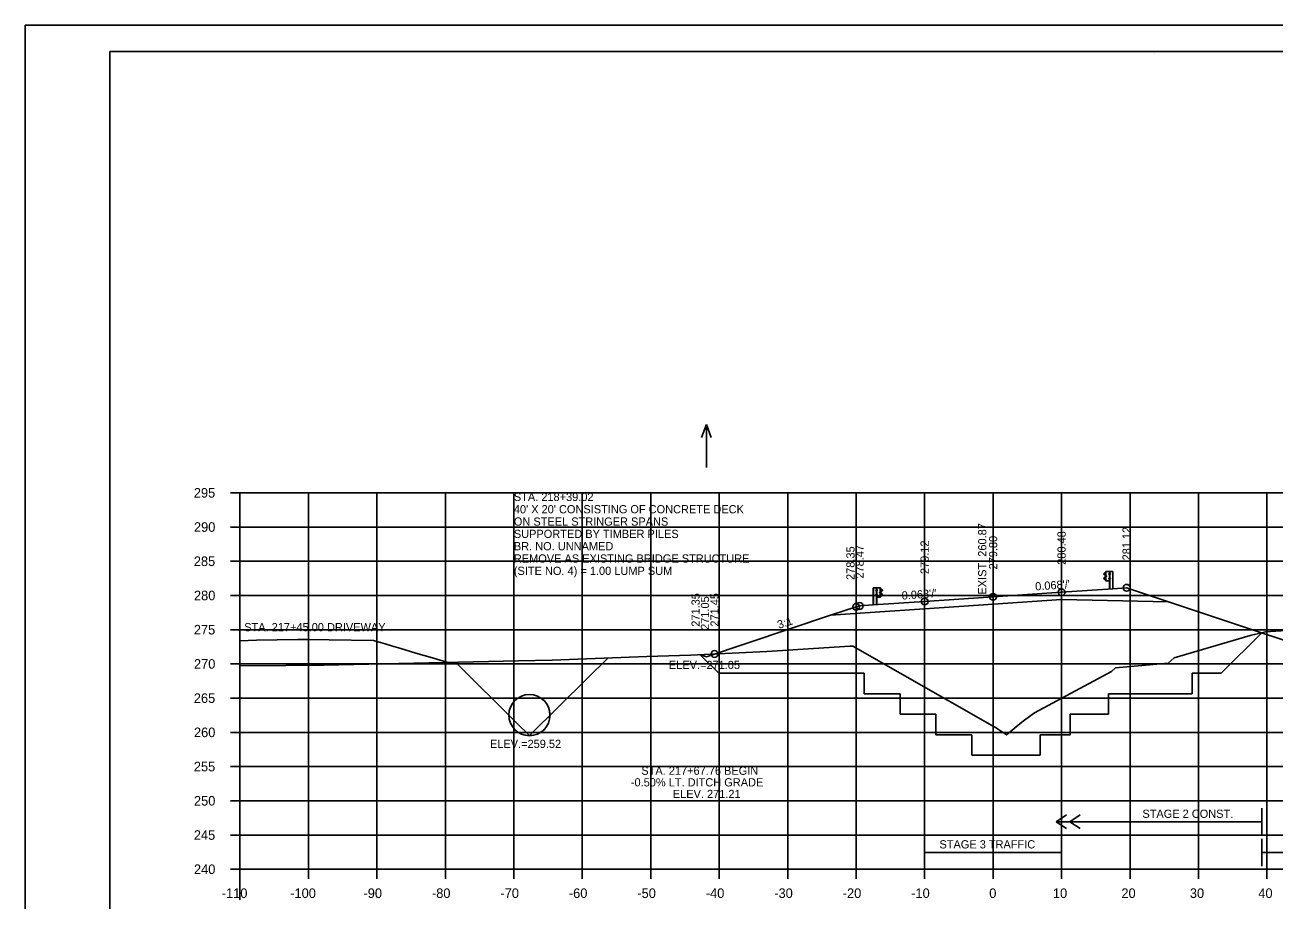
# Model space of a CAD drawing. Extents: x 4667 to 1632277, y -2100 to 724501.
# Drawn here: x 5635.8 to 5818.2, y -1024.9 to -897.1 of the extents above; entities that cross this region are included whole.
import ezdxf

# ---------------------------------------------------------------- set-up
doc = ezdxf.new("R2010")
doc.units = 0
for name, color, linetype in [('R_Alt Surface', 7, 'Continuous'), ('R_Axis', 7, 'Continuous'), ('R_Axis Annot', 7, 'Continuous'), ('R_Border', 7, 'Continuous'), ('R_Draft', 7, 'Continuous'), ('R_Drive', 7, 'Continuous'), ('R_Exist Surface', 7, 'Continuous'), ('R_Fin Surface', 7, 'Continuous'), ('R_Fin Surface Annot', 7, 'Continuous'), ('R_Grid', 7, 'Continuous'), ('R_No Plot', 7, 'Continuous'), ('R_Proposed CofA', 7, 'Continuous'), ('R_ROW', 7, 'Continuous'), ('R_Temp Easement', 7, 'Continuous'), ('R_Water', 7, 'Continuous'), ('R_Water Annot', 7, 'Continuous'), ('R_Xsect Elev', 7, 'Continuous')]:
    doc.layers.add(name, color=color, linetype=linetype)

msp = doc.modelspace()

# ---------------------------------------------------------------- linework, layer by layer
at = {"layer": 'R_Alt Surface'}
msp.add_lwpolyline([(5753.44, -983.33), (5767.18, -982.4), (5777.18, -981.72), (5787.18, -981.04), (5802.81, -981.35)], dxfattribs=at)
at = {"layer": 'R_Axis'}
for p, q in [((5665.78, -965.43), (5667.18, -965.43)), ((5667.18, -1020.43), (5667.18, -965.43)), ((5665.78, -970.43), (5667.18, -970.43)), ((5665.78, -975.43), (5667.18, -975.43)), ((5665.78, -980.43), (5667.18, -980.43)), ((5665.78, -985.43), (5667.18, -985.43)), ((5665.78, -990.43), (5667.18, -990.43)), ((5665.78, -995.43), (5667.18, -995.43)), ((5665.78, -1000.43), (5667.18, -1000.43)), ((5665.78, -1005.43), (5667.18, -1005.43)), ((5665.78, -1010.43), (5667.18, -1010.43)), ((5665.78, -1015.43), (5667.18, -1015.43)), ((5665.78, -1020.43), (5667.18, -1020.43)), ((5667.18, -1020.43), (5947.18, -1020.43)), ((5667.18, -1021.83), (5667.18, -1020.43)), ((5677.18, -1021.83), (5677.18, -1020.43)), ((5687.18, -1021.83), (5687.18, -1020.43)), ((5697.18, -1021.83), (5697.18, -1020.43)), ((5707.18, -1021.83), (5707.18, -1020.43)), ((5717.18, -1021.83), (5717.18, -1020.43)), ((5727.18, -1021.83), (5727.18, -1020.43)), ((5737.18, -1021.83), (5737.18, -1020.43)), ((5747.18, -1021.83), (5747.18, -1020.43)), ((5757.18, -1021.83), (5757.18, -1020.43)), ((5767.18, -1021.83), (5767.18, -1020.43)), ((5777.18, -1021.83), (5777.18, -1020.43)), ((5787.18, -1021.83), (5787.18, -1020.43)), ((5797.18, -1021.83), (5797.18, -1020.43)), ((5807.18, -1021.83), (5807.18, -1020.43)), ((5817.18, -1021.83), (5817.18, -1020.43))]:
    msp.add_line(p, q, dxfattribs=at)
at = {"layer": 'R_Border'}
for p, q in [((5648.18, -900.97), (5964.36, -900.97)), ((5648.18, -1106.43), (5648.18, -900.97)), ((5800.7, -901.23), (5800.7, -901.23)), ((5800.7, -901.23), (5800.7, -901.23))]:
    msp.add_line(p, q, dxfattribs=at)
at = {"layer": 'R_Draft'}
for p, q in [((5793.39, -977.25), (5793.52, -977.14)), ((5793.56, -977.49), (5793.39, -977.39)), ((5793.4, -977.26), (5793.53, -977.16)), ((5793.57, -977.47), (5793.4, -977.37)), ((5793.41, -977.83), (5793.57, -977.73)), ((5793.42, -977.85), (5793.58, -977.75)), ((5793.52, -977.14), (5793.63, -977.08)), ((5793.53, -977.16), (5793.62, -977.11)), ((5793.6, -977.67), (5793.6, -977.54)), ((5793.62, -977.67), (5793.62, -977.54)), ((5793.66, -978.29), (5793.66, -976.93)), ((5793.67, -977.67), (5793.67, -977.55)), ((5793.67, -977.55), (5793.72, -977.55)), ((5793.67, -977.58), (5793.72, -977.58)), ((5793.67, -977.64), (5793.72, -977.64)), ((5793.67, -977.64), (5793.72, -977.64)), ((5793.67, -977.67), (5793.72, -977.67)), ((5793.73, -977.66), (5793.73, -977.56)), ((5794.15, -977.23), (5794.1, -977.23)), ((5794.1, -977.23), (5794.1, -977.36)), ((5794.1, -977.3), (5794.16, -977.3)), ((5794.15, -977.36), (5794.1, -977.36)), ((5794.16, -976.93), (5794.17, -976.93)), ((5794.16, -976.93), (5794.23, -976.93)), ((5794.19, -979.44), (5794.19, -976.93)), ((5794.23, -977.35), (5794.23, -977.23)), ((5794.23, -977.23), (5794.28, -977.23)), ((5794.23, -977.26), (5794.28, -977.26)), ((5794.23, -977.32), (5794.27, -977.32)), ((5794.23, -977.32), (5794.28, -977.32)), ((5794.23, -977.35), (5794.28, -977.35)), ((5794.28, -977.34), (5794.28, -977.24)), ((5794.65, -976.93), (5794.65, -979.44)), ((5794.68, -976.93), (5794.68, -979.44)), ((5759.68, -979.31), (5759.68, -981.82)), ((5759.71, -979.31), (5759.71, -981.82)), ((5760.08, -979.72), (5760.08, -979.62)), ((5760.14, -979.61), (5760.09, -979.61)), ((5760.14, -979.64), (5760.09, -979.64)), ((5760.21, -979.31), (5760.14, -979.31)), ((5760.14, -979.73), (5760.14, -979.61)), ((5760.18, -981.82), (5760.18, -979.31)), ((5760.21, -979.31), (5760.2, -979.31)), ((5760.26, -979.68), (5760.21, -979.68)), ((5760.22, -979.61), (5760.27, -979.61)), ((5760.27, -979.61), (5760.27, -979.74)), ((5760.71, -980.67), (5760.71, -979.31)), ((5760.85, -979.52), (5760.74, -979.46)), ((5760.84, -979.54), (5760.75, -979.49)), ((5760.97, -979.64), (5760.84, -979.54)), ((5760.98, -979.63), (5760.85, -979.52)), ((5793.51, -978.09), (5793.38, -977.98)), ((5793.52, -978.08), (5793.4, -977.97)), ((5793.62, -978.15), (5793.51, -978.09)), ((5793.63, -978.13), (5793.52, -978.08)), ((5794.1, -978.04), (5794.1, -977.92)), ((5794.1, -977.92), (5794.15, -977.92)), ((5794.1, -977.98), (5794.16, -977.98)), ((5794.1, -978.04), (5794.15, -978.04)), ((5794.16, -978.29), (5794.19, -978.29)), ((5794.24, -978.04), (5794.24, -977.92)), ((5794.24, -977.92), (5794.29, -977.92)), ((5794.24, -977.95), (5794.29, -977.95)), ((5794.24, -978.01), (5794.28, -978.01)), ((5794.24, -978.01), (5794.29, -978.01)), ((5794.24, -978.04), (5794.29, -978.04)), ((5794.29, -978.03), (5794.29, -977.93)), ((5760.07, -980.41), (5760.07, -980.31)), ((5760.13, -980.3), (5760.08, -980.3)), ((5760.13, -980.33), (5760.08, -980.33)), ((5760.13, -980.39), (5760.08, -980.39)), ((5760.13, -980.42), (5760.08, -980.42)), ((5760.14, -979.7), (5760.09, -979.7)), ((5760.14, -979.73), (5760.09, -979.73)), ((5760.13, -980.39), (5760.09, -980.39)), ((5760.14, -979.7), (5760.1, -979.7)), ((5760.13, -980.42), (5760.13, -980.3)), ((5760.21, -980.67), (5760.17, -980.67)), ((5760.26, -980.36), (5760.21, -980.36)), ((5760.22, -979.74), (5760.27, -979.74)), ((5760.27, -980.3), (5760.22, -980.3)), ((5760.27, -980.42), (5760.22, -980.42)), ((5760.27, -980.42), (5760.27, -980.3)), ((5760.64, -980.04), (5760.64, -979.95)), ((5760.7, -979.93), (5760.65, -979.93)), ((5760.7, -979.96), (5760.65, -979.96)), ((5760.7, -980.03), (5760.65, -980.03)), ((5760.7, -980.03), (5760.65, -980.03)), ((5760.7, -980.06), (5760.65, -980.06)), ((5760.7, -980.06), (5760.7, -979.93)), ((5760.74, -980.51), (5760.84, -980.46)), ((5760.74, -980.53), (5760.86, -980.47)), ((5760.75, -980.05), (5760.75, -979.92)), ((5760.77, -980.06), (5760.77, -979.92)), ((5760.79, -979.85), (5760.97, -979.75)), ((5760.94, -980.23), (5760.79, -980.13)), ((5760.96, -980.21), (5760.8, -980.11)), ((5760.81, -979.88), (5760.98, -979.77)), ((5760.84, -980.46), (5760.97, -980.35)), ((5760.86, -980.47), (5760.98, -980.36))]:
    msp.add_line(p, q, dxfattribs=at)
for points in [[(5793.63, -976.93), (5793.64, -978.29), (5794.16, -978.29), (5794.16, -976.93)], [(5793.67, -977.53), (5793.67, -977.7), (5793.66, -977.7), (5793.66, -977.53)], [(5793.73, -977.58), (5793.73, -977.64), (5793.76, -977.64), (5793.76, -977.58)], [(5794.1, -977.23), (5794.1, -977.36), (5794.16, -977.36), (5794.16, -977.23)], [(5794.23, -977.21), (5794.23, -977.38), (5794.22, -977.38), (5794.22, -977.21)], [(5794.29, -977.26), (5794.29, -977.32), (5794.31, -977.32), (5794.31, -977.26)], [(5760.08, -979.64), (5760.08, -979.7), (5760.06, -979.7), (5760.06, -979.64)], [(5760.14, -979.59), (5760.14, -979.76), (5760.15, -979.76), (5760.15, -979.59)], [(5760.73, -979.31), (5760.73, -980.67), (5760.21, -980.67), (5760.21, -979.31)], [(5760.26, -979.61), (5760.26, -979.74), (5760.21, -979.74), (5760.21, -979.61)], [(5794.1, -977.92), (5794.1, -978.04), (5794.16, -978.04), (5794.16, -977.92)], [(5794.24, -977.9), (5794.24, -978.07), (5794.23, -978.07), (5794.23, -977.9)], [(5794.3, -977.95), (5794.3, -978.01), (5794.32, -978.01), (5794.32, -977.95)], [(5760.07, -980.33), (5760.07, -980.39), (5760.05, -980.39), (5760.05, -980.33)], [(5760.13, -980.28), (5760.13, -980.45), (5760.14, -980.45), (5760.14, -980.28)], [(5760.26, -980.3), (5760.26, -980.42), (5760.21, -980.42), (5760.21, -980.3)], [(5760.64, -979.96), (5760.64, -980.02), (5760.61, -980.02), (5760.61, -979.96)], [(5760.69, -979.91), (5760.69, -980.08), (5760.7, -980.08), (5760.7, -979.91)]]:
    msp.add_lwpolyline(points, close=True, dxfattribs=at)
for points in [[(5794.68, -976.93), (5794.23, -976.93), (5794.23, -979.44)], [(5759.68, -979.31), (5760.14, -979.31), (5760.14, -981.82)]]:
    msp.add_lwpolyline(points, dxfattribs=at)
for centre, radius, start, end in [((5793.43, -977.31), 0.0856, 122.0217, 240.7501), ((5793.47, -977.92), 0.109, 120.88, 214.7816), ((5793.43, -977.31), 0.062, 122.0217, 240.7501), ((5793.47, -977.92), 0.0854, 120.88, 214.7816), ((5793.53, -977.55), 0.0622, 4.9556, 61.894), ((5793.6, -977.62), 0.0453, 93.9303, 257.0446), ((5793.53, -977.55), 0.0865, 4.9556, 61.894), ((5793.55, -977.68), 0.0462, 293.1464, 8.2196), ((5793.55, -977.68), 0.0703, 293.1464, 8.2196), ((5793.71, -977.57), 0.022, 317.7756, 45.4255), ((5793.64, -977.61), 0.0922, 339.7423, 20.2577), ((5793.7, -977.66), 0.025, 323.3766, 39.0666), ((5794.26, -977.24), 0.022, 317.7756, 45.4255), ((5794.19, -977.29), 0.0922, 339.7423, 20.2577), ((5794.26, -977.34), 0.025, 323.3766, 39.0666), ((5760.11, -979.62), 0.022, 134.5745, 222.2244), ((5760.18, -979.67), 0.0922, 159.7423, 200.2577), ((5760.94, -979.7), 0.062, 299.2499, 57.9783), ((5760.94, -979.7), 0.0856, 299.2499, 57.9783), ((5794.27, -977.93), 0.022, 317.7756, 45.4255), ((5794.2, -977.98), 0.0922, 339.7423, 20.2577), ((5794.27, -978.03), 0.025, 323.3766, 39.0666), ((5760.1, -980.31), 0.022, 134.5745, 222.2244), ((5760.17, -980.36), 0.0922, 159.7423, 200.2577), ((5760.1, -980.41), 0.025, 140.9334, 216.6234), ((5760.11, -979.72), 0.025, 140.9334, 216.6234), ((5760.66, -979.95), 0.022, 134.5745, 222.2244), ((5760.73, -979.99), 0.0922, 159.7423, 200.2577), ((5760.67, -980.04), 0.025, 140.9334, 216.6234), ((5760.84, -979.93), 0.0865, 118.106, 175.0444), ((5760.82, -980.06), 0.0703, 171.7804, 246.8536), ((5760.84, -979.93), 0.0622, 118.106, 175.0444), ((5760.77, -980), 0.0453, 282.9554, 86.0697), ((5760.82, -980.06), 0.0462, 171.7804, 246.8536), ((5760.9, -980.3), 0.0854, 325.2184, 59.12), ((5760.9, -980.3), 0.109, 325.2184, 59.12)]:
    msp.add_arc(centre, radius, start, end, dxfattribs=at)
at = {"layer": 'R_Drive'}
msp.add_lwpolyline([(5667.18, -987.04), (5669.58, -986.98), (5675.63, -986.85), (5677.1, -986.87), (5680.22, -986.91), (5686.68, -987), (5688.39, -987.51), (5689.32, -987.79), (5690.68, -988.19), (5692.88, -988.85), (5695.3, -989.55), (5697.56, -990.21)], dxfattribs=at)
at = {"layer": 'R_Exist Surface'}
msp.add_lwpolyline([(5667.18, -990.7), (5673.88, -990.67), (5679.47, -990.62), (5683.82, -990.53), (5707.87, -989.97), (5712.76, -989.86), (5726.62, -989.37), (5732.99, -989.15), (5744.12, -988.61), (5756.26, -987.86), (5756.71, -987.83), (5777.42, -999.69), (5777.79, -999.89), (5777.84, -999.9), (5779.15, -1000.78), (5781.39, -998.92), (5782.88, -997.83), (5783.22, -997.6), (5794.48, -991.54), (5795.07, -990.99), (5802.75, -990.33), (5803.65, -989.56), (5814.73, -986.26), (5816.96, -985.76), (5822.23, -985.39)], dxfattribs=at)
at = {"layer": 'R_Fin Surface'}
msp.add_lwpolyline([(5734.4, -989.08), (5735.3, -989.38), (5753.44, -983.33), (5757.18, -982.08), (5757.68, -981.96), (5759.68, -981.82), (5767.18, -981.31), (5777.18, -980.63), (5787.18, -979.95), (5794.68, -979.44), (5796.68, -979.31), (5802.81, -981.35), (5862.19, -1001.14), (5897.19, -1001.14), (5918.54, -994.02)], dxfattribs=at)
at = {"layer": 'R_Grid'}
for p, q in [((5667.18, -965.43), (5947.18, -965.43)), ((5667.18, -1020.43), (5667.18, -965.43)), ((5677.18, -1020.43), (5677.18, -965.43)), ((5687.18, -1020.43), (5687.18, -965.43)), ((5697.18, -1020.43), (5697.18, -965.43)), ((5707.18, -1020.43), (5707.18, -965.43)), ((5717.18, -1020.43), (5717.18, -965.43)), ((5727.18, -1020.43), (5727.18, -965.43)), ((5737.18, -1020.43), (5737.18, -965.43)), ((5747.18, -1020.43), (5747.18, -965.43)), ((5757.18, -1020.43), (5757.18, -965.43)), ((5767.18, -1020.43), (5767.18, -965.43)), ((5777.18, -1020.43), (5777.18, -965.43)), ((5787.18, -1020.43), (5787.18, -965.43)), ((5797.18, -1020.43), (5797.18, -965.43)), ((5807.18, -1020.43), (5807.18, -965.43)), ((5817.18, -1020.43), (5817.18, -965.43)), ((5667.18, -970.43), (5947.18, -970.43)), ((5667.18, -975.43), (5947.18, -975.43)), ((5667.18, -980.43), (5947.18, -980.43)), ((5667.18, -985.43), (5947.18, -985.43)), ((5667.18, -990.43), (5947.18, -990.43)), ((5667.18, -995.43), (5947.18, -995.43)), ((5667.18, -1000.43), (5947.18, -1000.43)), ((5667.18, -1005.43), (5947.18, -1005.43)), ((5667.18, -1010.43), (5947.18, -1010.43)), ((5667.18, -1015.43), (5947.18, -1015.43)), ((5667.18, -1020.43), (5947.18, -1020.43))]:
    msp.add_line(p, q, dxfattribs=at)
at = {"layer": 'R_No Plot'}
for p, q in [((5635.78, -897.08), (5969.12, -897.08)), ((5667.18, -1021.83), (5667.18, -1024.9))]:
    msp.add_line(p, q, dxfattribs=at)
for points in [[(5635.78, -897.08), (5969.12, -897.08), (5969.12, -1110.41), (5635.78, -1110.41)], [(5882.1, -900.97), (5901.72, -900.97), (5901.72, -910.85), (5917.84, -910.85), (5941.04, -910.85), (5941.04, -935.18), (5964.36, -935.18), (5964.36, -1106.43), (5648.18, -1106.43), (5648.18, -900.97)]]:
    msp.add_lwpolyline(points, close=True, dxfattribs=at)
msp.add_lwpolyline([(5698.67, -990.19), (5707.62, -999.08), (5709.46, -1000.91), (5717.99, -992.44), (5720.89, -989.57)], dxfattribs=at)
for centre, radius in [((5787.18, -979.95), 0.5), ((5796.68, -979.31), 0.5), ((5796.68, -979.31), 0.5), ((5757.68, -981.96), 0.5), ((5767.18, -981.31), 0.5), ((5777.18, -980.63), 0.5), ((5757.18, -982.08), 0.5), ((5736.5, -988.98), 0.5), ((5709.46, -997.91), 3.01)]:
    msp.add_circle(centre, radius, dxfattribs=at)
at = {"layer": 'R_Proposed CofA'}
for p, q in [((5786.41, -1013.5), (5787.91, -1012.5)), ((5788.41, -1013.5), (5789.91, -1012.5)), ((5786.41, -1013.5), (5787.91, -1014.5)), ((5788.41, -1013.5), (5789.91, -1014.5))]:
    msp.add_line(p, q, dxfattribs=at)
at = {"layer": 'R_ROW'}
for p, q in [((5816.41, -985.88), (5810.51, -991.78)), ((5734.4, -989.08), (5737.1, -991.78)), ((5758.37, -991.78), (5737.1, -991.78)), ((5758.37, -991.78), (5758.37, -994.78)), ((5806.27, -991.78), (5806.27, -994.78)), ((5806.27, -991.78), (5810.51, -991.78)), ((5763.6, -994.78), (5758.37, -994.78)), ((5763.6, -994.78), (5763.6, -997.78)), ((5794.03, -994.78), (5794.03, -997.78)), ((5794.03, -994.78), (5806.27, -994.78)), ((5768.84, -997.78), (5763.6, -997.78)), ((5768.84, -997.78), (5768.84, -1000.78)), ((5788.45, -997.78), (5788.45, -1000.78)), ((5788.45, -997.78), (5794.03, -997.78)), ((5768.84, -1000.78), (5774.08, -1000.78)), ((5774.08, -1003.78), (5774.08, -1000.78)), ((5784.08, -1000.78), (5784.08, -1003.78)), ((5784.08, -1000.78), (5788.45, -1000.78)), ((5784.08, -1003.78), (5774.08, -1003.78))]:
    msp.add_line(p, q, dxfattribs=at)
at = {"layer": 'R_Temp Easement'}
for p, q in [((5816.41, -1015.5), (5816.41, -1011.5)), ((5816.41, -1013.5), (5786.41, -1013.5)), ((5767.18, -1020), (5767.18, -1016)), ((5787.18, -1020), (5787.18, -1016)), ((5816.41, -1020), (5816.41, -1016)), ((5787.18, -1018), (5767.18, -1018)), ((5816.41, -1018), (5846.41, -1018))]:
    msp.add_line(p, q, dxfattribs=at)
at = {"layer": 'R_Water'}
msp.add_circle((5709.46, -997.91), 3, dxfattribs=at)
at = {"layer": 'R_Water Annot'}
for p, q in [((5735.3, -955.43), (5734.6, -957.35)), ((5735.3, -961.71), (5735.3, -955.43)), ((5735.3, -955.43), (5736, -957.35))]:
    msp.add_line(p, q, dxfattribs=at)

# ---------------------------------------------------------------- texts
at = {"layer": 'R_Axis Annot'}
for s, p in [('295', (5660.44, -966.13)), ('290', (5660.46, -971.13)), ('285', (5660.44, -976.13)), ('280', (5660.46, -981.13)), ('275', (5660.44, -986.13)), ('270', (5660.46, -991.13)), ('265', (5660.44, -996.13)), ('260', (5660.46, -1001.13)), ('255', (5660.44, -1006.13)), ('250', (5660.46, -1011.13)), ('245', (5660.44, -1016.13)), ('240', (5660.46, -1021.13)), ('-110', (5664.52, -1024.63)), ('-100', (5674.52, -1024.63)), ('-90', (5685.22, -1024.63)), ('-80', (5695.22, -1024.63)), ('-70', (5705.22, -1024.63)), ('-60', (5715.22, -1024.63)), ('-50', (5725.22, -1024.63)), ('-40', (5735.22, -1024.63)), ('-30', (5745.22, -1024.63)), ('-20', (5755.22, -1024.63)), ('-10', (5765.22, -1024.63)), ('0', (5776.62, -1024.63)), ('10', (5785.92, -1024.63)), ('20', (5795.92, -1024.63)), ('30', (5805.92, -1024.63)), ('40', (5815.92, -1024.63))]:
    msp.add_text(s, height=1.4, dxfattribs=at).set_placement(p)
at = {"layer": 'R_Drive'}
msp.add_text('STA. 217+45.00 DRIVEWAY', height=1.2, dxfattribs=at).set_placement((5667.8, -985.66))
at = {"layer": 'R_Fin Surface Annot'}
for s, rotation, p in [('281.12', 90, (5797.28, -975.31)), ('279.80', 90, (5777.78, -976.63)), ('280.48', 90, (5787.78, -975.95)), ('278.35', 90, (5756.95, -978.16)), ('278.47', 90, (5758.28, -977.96)), ('279.12', 90, (5767.78, -977.31)), ("0.068'/'", 3.8912, (5763.87, -981.04)), ("0.068'/'", 3.8912, (5783.37, -979.71)), ('271.35', 90, (5734.33, -985)), ('271.05', 90, (5735.7, -985.46)), ('3:1', 18.4349, (5745.9, -985.32))]:
    msp.add_text(s, height=1.2, rotation=rotation, dxfattribs=at).set_placement(p)
at = {"layer": 'R_No Plot'}
msp.add_text('271.45', height=1.2, rotation=90, dxfattribs=at).set_placement((5737.1, -984.98))
at = {"layer": 'R_Temp Easement'}
msp.add_text('EXIST. 260.87', height=1.2, rotation=90, dxfattribs=at).set_placement((5776.2, -980.3))
for s, p in [('STAGE 2 CONST.', (5798.99, -1012.92)), ('STAGE 3 TRAFFIC', (5769.35, -1017.39))]:
    msp.add_text(s, height=1.1985, dxfattribs=at).set_placement(p)
at = {"layer": 'R_Water Annot'}
for s, p in [('STA. 218+39.02', (5707.18, -966.63)), ("40' X 20' CONSISTING OF CONCRETE DECK ", (5707.18, -968.43)), ('ON STEEL STRINGER SPANS', (5707.18, -970.23)), ('SUPPORTED BY TIMBER PILES', (5707.18, -972.03)), ('BR. NO. UNNAMED', (5707.18, -973.83)), ('REMOVE AS EXISTING BRIDGE STRUCTURE', (5707.18, -975.63)), ('(SITE NO. 4) = 1.00 LUMP SUM', (5707.18, -977.43)), ('STA. 217+67.76 BEGIN', (5725.8, -1006.63)), ('-0.50% LT. DITCH GRADE', (5724.27, -1008.33)), ('ELEV. 271.21', (5730.4, -1010.03))]:
    msp.add_text(s, height=1.2, dxfattribs=at).set_placement(p)
at = {"layer": 'R_Xsect Elev'}
for s, p in [('ELEV.=271.05', (5729.82, -991.18)), ('ELEV.=259.52', (5703.69, -1002.71))]:
    msp.add_text(s, height=1.2, dxfattribs=at).set_placement(p)

doc.saveas('drawing.dxf')
